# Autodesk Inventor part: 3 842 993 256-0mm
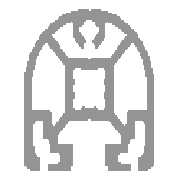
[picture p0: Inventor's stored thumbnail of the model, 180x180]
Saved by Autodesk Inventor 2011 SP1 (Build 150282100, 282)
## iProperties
Category: End -/-
Created: 2011-02
Part Number: 3 842 993 256-0mm
Document SubType Name: Modeling
Designer: SRW
Density: 2.71 g/cm^3
Categories: <MemberInstance><Categories><Category DisplayName="Structural Shapes" InternalName="089c4875-fa83-4c05-b084-43b9cc11f5ed" Mnemonic="GRDR"><CategoryParameter Dis
Stock Number: 3 842 993 256
Description: PROFILE 40x40HR, -/-
Material: Aluminum-6061
Mass: 37.329 g
Surface Area: 128.849 cm^2
Volume: 13.7745 cm^3
G_L: 25.000 mm
Author: SRW
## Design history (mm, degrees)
node "Blocks"
  sketch "40X40HR"
    geometry: L1 (15.483, 16.091)-(16.484, 16.091); L2 (18.983, 17.59)-(18.983, 15.386); L3 (20.692, 14.68)-(23.337, 17.335); L4 (25.784, 9.59)-(21.134, 9.59); L5 (19.696, 8.09)-(20.984, 8.09); L6 (25.984, 5.39)-(25.984, 9.39); L7 (25.484, 5.09)-(25.684, 5.09); L8 (25.184, 4.09)-(25.184, 4.79); L9 (18.484, 3.59)-(24.684, 3.59); L10 (20.984, 5.09)-(18.984, 5.09); L11 (18.484, 4.59)-(18.484, 3.59); L12 (15.637, 3.59)-(15.499, 6.224); L13 (13.983, 3.59)-(15.637, 3.59); L14 (50.683, 23.59)-(50.977, 24.098); L15 (50.983, 23.07)-(50.683, 23.59); L16 (48.983, 18.59)-(48.983, 23.59); L17 (45.483, 16.091)-(46.483, 16.091); L18 (43.483, 18.09)-(48.483, 18.09); L19 (42.983, 15.386)-(42.983, 17.59); L20 (35.184, 28.79)-(33.572, 28.79); L21 (36.184, 26.179)-(36.184, 27.79); L22 (38.484, 29.469)-(38.484, 24.163); L23 (43.934, 35.126)-(38.63, 29.822); L24 (31.082, 16.332)-(31.456, 16.117); L25 (30.511, 16.117)-(30.884, 16.332); L26 (25.783, 21.001)-(25.783, 19.39); L27 (33.055, 18.825)-(33.114, 18.69); L28 (28.853, 18.69)-(28.911, 18.825); L29 (26.783, 18.39)-(28.394, 18.39); L30 (25.004, 16.09)-(30.411, 16.09); L31 (26.084, 25.72)-(26.218, 25.662); L32 (28.911, 28.355)-(28.853, 28.489); L33 (25.783, 27.79)-(25.783, 26.179); L34 (28.394, 28.79)-(26.783, 28.79); L35 (30.51, 31.063)-(30.883, 30.848); L36 (23.483, 24.163)-(23.483, 29.469); L37 (26.218, 21.518)-(26.084, 21.459); L38 (12.983, 23.59)-(12.983, 18.59); L39 (23.483, 17.688)-(23.483, 23.017); L40 (23.51, 23.117)-(23.725, 23.49); L41 (23.725, 23.69)-(23.51, 24.063); L42 (23.337, 29.822)-(18.033, 35.126); L43 (13.483, 18.09)-(18.483, 18.09); L44 (11.283, 23.59)-(10.983, 23.07); L45 (10.99, 24.098)-(11.283, 23.59); L46 (29.626, 35.179)-(29.2, 34.265); L47 (25.104, 31.09)-(30.41, 31.09); L48 (27.983, 37.09)-(28.288, 37.09); L49 (27.783, 38.89)-(27.783, 37.29); L50 (28.288, 39.09)-(27.983, 39.09); L51 (19.491, 36.496)-(24.751, 31.237); L52 (20.993, 12.148)-(24.862, 16.031); L53 (20.934, 9.79)-(20.934, 12.007); L54 (13.483, 9.523)-(13.483, 14.091); L55 (10.983, 23.07)-(10.983, 6.59); L56 (16.984, 15.591)-(16.984, 12.183); L57 (37.104, 16.031)-(40.974, 12.148); L58 (41.032, 12.007)-(41.032, 9.79); L59 (46.467, 6.224)-(46.329, 3.59); L60 (46.329, 3.59)-(47.983, 3.59); L61 (44.983, 12.183)-(44.983, 15.591); L62 (48.483, 14.091)-(48.483, 9.523); L63 (50.983, 6.59)-(50.983, 23.07); L64 (40.982, 8.09)-(42.271, 8.09)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; A1 r 1 centre (19.983, 15.386) between (18.983, 15.386) and (20.692, 14.68); A2 r 0.5 centre (18.483, 17.59) between (18.983, 17.59) and (18.483, 18.09); A3 r 0.5 centre (22.983, 17.688) between (23.337, 17.335) and (23.483, 17.688); A4 r 0.5 centre (16.484, 15.591) between (16.984, 15.591) and (16.484, 16.091); A5 r 0.2 centre (25.784, 9.39) between (25.984, 9.39) and (25.784, 9.59); A6 r 0.5 centre (19.696, 8.59) between (19.201, 8.667) and (19.696, 8.09); A7 r 0.5 centre (13.983, 9.523) between (13.483, 9.523) and (13.613, 9.187); A8 r 0.5 centre (13.242, 8.852) between (13.741, 8.888) and (13.613, 9.187); A9 r 1.5 centre (20.984, 6.59) between (20.984, 5.09) and (20.984, 8.09); A10 r 0.3 centre (25.684, 5.39) between (25.684, 5.09) and (25.984, 5.39); A11 r 0.3 centre (25.484, 4.79) between (25.484, 5.09) and (25.184, 4.79); A12 r 0.5 centre (24.684, 4.09) between (24.684, 3.59) and (25.184, 4.09); A13 r 2.75 centre (16.483, 9.09) between (13.741, 8.888) and (15.228, 6.643); A14 r 0.5 centre (15, 6.198) between (15.499, 6.224) and (15.228, 6.643); A15 r 0.5 centre (18.984, 4.59) between (18.984, 5.09) and (18.484, 4.59); A16 r 3 centre (13.983, 6.59) between (10.983, 6.59) and (13.983, 3.59); A17 r 0.5 centre (48.483, 18.59) between (48.483, 18.09) and (48.983, 18.59); A18 r 0.5 centre (45.483, 15.591) between (45.483, 16.091) and (44.983, 15.591); A19 r 0.5 centre (43.483, 17.59) between (43.483, 18.09) and (42.983, 17.59); A20 r 1 centre (35.184, 27.79) between (36.184, 27.79) and (35.184, 28.79); A21 r 0.5 centre (38.984, 29.469) between (38.63, 29.822) and (38.484, 29.469); A22 r 0.5 centre (44.287, 34.773) between (44.664, 35.102) and (43.934, 35.126); A23 r 17.5 centre (31.483, 23.59) between (48.983, 23.59) and (44.664, 35.102); A24 r 0.2 centre (38.414, 23.59) between (38.241, 23.69) and (38.241, 23.49); A25 r 0.2 centre (31.556, 16.29) between (31.456, 16.117) and (31.556, 16.09); A26 r 0.2 centre (30.982, 16.159) between (31.082, 16.332) and (30.983, 16.359); A27 r 0.2 centre (30.984, 16.159) between (30.983, 16.359) and (30.884, 16.332); A28 r 0.5 centre (26.283, 21.001) between (26.084, 21.459) and (25.783, 21.001); A29 r 0.2 centre (32.872, 18.745) between (33.055, 18.825) and (32.799, 18.931); A30 r 5 centre (30.983, 23.59) between (29.167, 18.931) and (32.799, 18.931); A31 r 0.5 centre (33.572, 18.89) between (33.114, 18.69) and (33.572, 18.39); A32 r 0.2 centre (29.095, 18.745) between (29.167, 18.931) and (28.911, 18.825); A33 r 1 centre (26.783, 19.39) between (25.783, 19.39) and (26.783, 18.39); A34 r 0.5 centre (28.394, 18.89) between (28.394, 18.39) and (28.853, 18.69); A35 r 0.2 centre (30.411, 16.29) between (30.411, 16.09) and (30.511, 16.117); A36 r 0.2 centre (26.138, 21.701) between (26.218, 21.518) and (26.325, 21.774); A37 r 0.2 centre (23.552, 23.59) between (23.725, 23.49) and (23.725, 23.69); A38 r 5 centre (30.983, 23.59) between (26.325, 25.406) and (26.325, 21.774); A39 r 0.2 centre (26.138, 25.478) between (26.325, 25.406) and (26.218, 25.662); A40 r 0.5 centre (26.283, 26.179) between (25.783, 26.179) and (26.084, 25.72); A41 r 5 centre (30.983, 23.59) between (32.799, 28.248) and (29.167, 28.248); A42 r 0.2 centre (29.095, 28.435) between (28.911, 28.355) and (29.167, 28.248); A43 r 0.5 centre (28.394, 28.29) between (28.853, 28.489) and (28.394, 28.79); A44 r 0.2 centre (30.983, 31.021) between (30.983, 30.821) and (31.083, 30.848); A45 r 0.2 centre (30.983, 31.021) between (30.883, 30.848) and (30.983, 30.821); A46 r 0.2 centre (30.41, 30.89) between (30.51, 31.063) and (30.41, 31.09); A47 r 1 centre (26.783, 27.79) between (26.783, 28.79) and (25.783, 27.79); A48 r 0.5 centre (22.983, 29.469) between (23.483, 29.469) and (23.337, 29.822); A49 r 0.5 centre (13.483, 18.59) between (12.983, 18.59) and (13.483, 18.09); A50 r 0.2 centre (23.683, 23.017) between (23.51, 23.117) and (23.483, 23.017); A51 r 0.2 centre (23.683, 24.163) between (23.483, 24.163) and (23.51, 24.063); A52 r 17.5 centre (30.483, 23.59) between (17.303, 35.102) and (12.983, 23.59); A53 r 0.5 centre (17.679, 34.773) between (18.033, 35.126) and (17.303, 35.102); A54 r 19.5 centre (30.483, 23.59) between (30.464, 43.09) and (10.99, 24.098); A55 r 0.5 centre (25.104, 31.59) between (24.751, 31.237) and (25.104, 31.09); A56 r 0.5 centre (19.845, 36.85) between (19.532, 37.24) and (19.491, 36.496); A57 r 0.5 centre (28.747, 34.476) between (28.483, 34.051) and (29.2, 34.265); A58 r 0.5 centre (29.173, 35.391) between (29.626, 35.179) and (29.452, 35.806); A59 r 0.2 centre (27.983, 37.29) between (27.783, 37.29) and (27.983, 37.09); A60 r 0.2 centre (28.288, 36.89) between (28.471, 36.971) and (28.288, 37.09); A61 r 2.75 centre (30.983, 38.09) between (28.471, 36.971) and (29.452, 35.806); A62 r 17.5 centre (30.483, 23.59) between (25.046, 40.224) and (19.532, 37.24); A63 r 0.2 centre (27.983, 38.89) between (27.983, 39.09) and (27.783, 38.89); A64 r 1 centre (25.356, 39.273) between (26.335, 39.067) and (25.046, 40.224)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; 1 further point
    constraints: 234 point on circle, 180 end point, 117 centre point, 1 coincident
node "Start Plane"
node "End Plane"
sketch "Sketch1"
  geometry: 1 further point
  constraints: 1 other
extrude "Body" new body sketch "Sketch1" stored distance "d4" = 0.13; taper "d5" = 0 deg
node "Driven Length"
  sketch "Sketch51"
    geometry: L1 (0, 0)-(10, 0) reference
    constraints: 2 end point, 1 horizontal
  workplane "Work Plane22"
  sketch "Sketch52"
    geometry: L1 (-28, 0)-(28, 0) reference; L2 (-28, 25)-(28, 25) reference
    dimensions: "d7" = 25 distance between parallel lines of L1 L2 (derived)
sketch "Sketch9"
  geometry: 1 further point
hole "M12/-" sketch "Sketch9" at (0, 0) diameter "d17" = 10.106; stored, may be unused: countersink angle "d21" = 90 deg, drill point angle "d23" = 118 deg; dims "d18" = 6, "d19" = 4, "d20" = 2, "d22" = 55
sketch "Sketch10"
  geometry: 1 further point
hole "-/M12" sketch "Sketch10" at (0, 0) diameter "d24" = 10.106; stored, may be unused: countersink angle "d28" = 90 deg, drill point angle "d30" = 118 deg; dims "d25" = 6, "d26" = 4, "d27" = 2, "d29" = 55
sketch "Sketch11"
  geometry: L1 (-13.7, 0)-(12.2, 0) reference; C1 r 8.5 at (0, 20); 1 further point
  constraints: 1 centre point, 1 vertical alignment
  dimensions: "d31" = 20 distance from line of C1.centre L1; "d32" = 17 diameter of C1
extrude "D17/-" cut sketch "Sketch11" stored distance "d33" = 10; taper "d34" = 0 deg
sketch "Sketch12"
  geometry: L1 (-13.7, 25)-(12.2, 25) reference; C1 r 8.5 at (0, 5); 1 further point
  constraints: 1 centre point, 1 vertical alignment
  dimensions: "d35" = 17 diameter of C1; "d36" = 20 distance from line of L1 C1.centre
extrude "-/D17" cut sketch "Sketch12" stored distance "d37" = 10; taper "d38" = 0 deg
sketch "Sketch13"
  geometry: L1 (-12.98, 0)-(7.88, 0) reference; C1 r 4.9 at (0, 20); 1 further point
  constraints: 1 centre point, 1 vertical alignment
  dimensions: "d39" = 9.8 diameter of C1; "d40" = 20 distance from line of C1.centre L1
extrude "D9.8/-" cut sketch "Sketch13" stored distance "d41" = 10; taper "d42" = 0 deg
sketch "Sketch14"
  geometry: L1 (-12.98, 25)-(7.88, 25) reference; C1 r 4.9 at (0, 5); 1 further point
  constraints: 1 centre point, 1 vertical alignment
  dimensions: "d43" = 9.8 diameter of C1; "d44" = 20 distance from line of L1 C1.centre
extrude "-/D9.8" cut sketch "Sketch14" stored distance "d45" = 10; taper "d46" = 0 deg
sketch "Sketch15"
  geometry: L1 (-6.86, 25)-(6.86, 25) reference; C1 r 4.9 at (0, 5); 1 further point
  constraints: 1 centre point, 1 vertical alignment
  dimensions: "d47" = 9.8 diameter of C1; "d48" = 20 distance from line of L1 C1.centre
extrude "-/D9.8VS" cut sketch "Sketch15" stored distance "d49" = 10; taper "d50" = 0 deg
sketch "Sketch26"
  geometry: L1 (-6.86, 0)-(6.86, 0) reference; C1 r 4.9 at (0, 20); 1 further point
  constraints: 1 centre point, 1 vertical alignment
  dimensions: "d62" = 9.8 diameter of C1; "d65" = 20 distance from line of L1 C1.centre
extrude "D9.8VS/-" cut sketch "Sketch26" stored distance "d63" = 10; taper "d64" = 0 deg
sketch "Sketch37"
  geometry: L1 (-11.9, 0)-(11.9, 0) reference; L2 (-11.9, 25)-(11.9, 25) reference; C1 r 8.5 at (0, 20); 1 further point
  constraints: 1 centre point, 1 vertical alignment
  dimensions: "d76" = 20 distance from line of C1.centre L1; "d77" = 17 diameter of C1
extrude "D17VS/-" cut sketch "Sketch37" stored distance "d78" = 10; taper "d79" = 0 deg
sketch "Sketch38"
  geometry: L1 (-11.9, 25)-(11.9, 25) reference; C1 r 8.5 at (0, 5); 1 further point
  constraints: 1 centre point, 1 vertical alignment
  dimensions: "d80" = 17 diameter of C1; "d81" = 20 distance from line of L1 C1.centre
extrude "-/D17VS" cut sketch "Sketch38" stored distance "d82" = 10; taper "d83" = 0 deg
body "Solid1"
node "40X40HR:1"
other parameters: "Length" = 25, "G_OFFSET_START" = 0 [user parameter; used in 2 equation terms], "G_OFFSET_END" = 0 [user parameter; used in 2 equation terms], "d2" = 0 (computed from G_OFFSET_START), "d3" = 25 (= Length + G_OFFSET_END), "G_L" = 25 (= d7) [user parameter], "Length2" = 25 (= G_OFFSET_START + Length + G_OFFSET_END) [user parameter], "d96" = 90 deg
